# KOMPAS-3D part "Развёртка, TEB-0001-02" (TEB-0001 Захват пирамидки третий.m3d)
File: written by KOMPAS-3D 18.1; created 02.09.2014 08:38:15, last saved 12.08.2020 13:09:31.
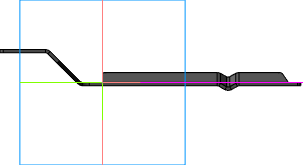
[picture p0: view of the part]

Document properties: Автор: user; Полное имя файла: F:\Чертежи\ЧАЙ\TSUBAKI\TEB\TEB-0001 и TEB-0001-01\TEB-0001 Захват пирамидки третий.m3d

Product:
- Part/product: Развёртка  | designation TEB-0001-02
    Материал: Лист$d1 ГОСТ 19904-90;12Х18Н9Т-Н1 ГОСТ 7350-77$ (density 7900 kg/m3)
    Масса: 0.028285
    source file: TEB-0001 Захват пирамидки третий.cdw
- Part/product: Захват пирамидки третий (дальний)  | designation TEB-0001-01
    Материал: Лист$d1 ГОСТ 19904-90;12Х18Н9Т-Н1 ГОСТ 7350-77$ (density 7900 kg/m3)
    Масса: 0.0283916
- Part/product: Захват пирамидки третий (ближний)  | designation TEB-0001
    Материал: Лист$d1 ГОСТ 19904-90;12Х18Н9Т-Н1 ГОСТ 7350-77$ (density 7900 kg/m3)
    Масса: 0.0283916
    source file: TEB-0001 Захват пирамидки третий.cdw

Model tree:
1. Эскиз:1
2. Листовое тело:1
     Расстояние 1 = 40
3. Сгиб(1) - Листовое тело:1
     Радиус сгиба = 1; Коэффициент = 0.421; Величина сгиба = 10
4. Сгиб(2) - Листовое тело:1
     Радиус сгиба = 1; Коэффициент = 0.421; Величина сгиба = 10
5. Сгиб(3) - Листовое тело:1
     Радиус сгиба = 1; Коэффициент = 0.421; Величина сгиба = 10
6. Эскиз:2  (with: Листовое тело:1)
7. Вырез в листовом теле:1
     Глубина выреза = 10
8. Эскиз:3  (with: Листовое тело:1)
9. Листовое тело:2
     Расстояние 1 = 40.5
10. Эскиз:4  (with: Листовое тело:2)
11. Вырез в листовом теле:2
     Глубина выреза = 10
12. Эскиз:7  (with: Листовое тело:2, Вырез в листовом теле:2)
13. Сгиб по линии:1
14. Сгиб(1) - Сгиб по линии:1  (with: Листовое тело:2)
     Радиус сгиба = 1; Коэффициент = 0.421; Величина сгиба = 10; Толщина листового тела = 1; Угол сгиба = 45
15. Эскиз:8  (with: Листовое тело:2)
16. Сгиб по линии:2
17. Сгиб(1) - Сгиб по линии:2  (with: Листовое тело:2)
     Радиус сгиба = 1; Коэффициент = 0.421; Величина сгиба = 10; Толщина листового тела = 1; Угол сгиба = 45
18. Эскиз:9  (with: Листовое тело:2)
19. Вырез в листовом теле:3
     Глубина выреза = 10
20. Эскиз:10  (with: Листовое тело:2, Вырез в листовом теле:3)
21. Вырез в листовом теле:4
     Глубина выреза = 10
22. Эскиз:11  (with: Листовое тело:2, Листовое тело:1)
23. Сгиб по линии:3
24. Сгиб(1) - Сгиб по линии:3  (with: Листовое тело:2)
     Радиус сгиба = 1; Коэффициент = 0.421; Величина сгиба = 10; Толщина листового тела = 1; Угол сгиба = 15
25. Сгиб по линии:4
26. Сгиб(1) - Сгиб по линии:4  (with: Листовое тело:1)
     Радиус сгиба = 1; Коэффициент = 0.421; Величина сгиба = 10; Толщина листового тела = 1; Угол сгиба = 15
27. Эскиз:12  (with: Листовое тело:1, Сгиб по линии:3, Сгиб по линии:4)
28. Вырезать элемент выдавливания:1  (with: Сгиб по линии:3)
     Расстояние 1 = 12
29. Эскиз:13  (with: Листовое тело:1)
30. Листовое тело:3
     Расстояние 2 = 11.628
31. Сгиб(1) - Листовое тело:3
     Радиус сгиба = 1; Коэффициент = 0.421; Величина сгиба = 10
32. Сгиб(2) - Листовое тело:3
     Радиус сгиба = 1; Коэффициент = 0.421; Величина сгиба = 10
33. Сгиб(3) - Листовое тело:3
     Радиус сгиба = 1; Коэффициент = 0.421; Величина сгиба = 10
34. Эскиз:14  (with: Сгиб по линии:4, Вырезать элемент выдавливания:1, Сгиб по линии:3)
35. Эскиз:15  (with: Листовое тело:3)
36. Операция по сечениям:1
     Толщина стенки 1 = 1; Толщина стенки 2 = 1
37. Скругление:1  (with: Вырез в листовом теле:3, Листовое тело:1, Вырез в листовом теле:1)
     Радиус = 1
38. Развертка  (with: Листовое тело:2)  (labels: Лист$d1 ГОСТ 19904-90;12Х18Н9Т-Н1 ГОСТ 7350-77$; TEB-0001|SM_Thickness; TEB-0001|SM_Radius; TEB-0001|SM_K)
39. Эскиз:16
40. Листовое тело:4
     Расстояние 1 = 10; Радиус сгиба = 1

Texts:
  TEB-0001
  TEB-0001|SM_BA
  TEB-0001|SM_BD
  TEB-0001|SM_Angle
  TEB-0001|SM_H
  TEB-0001|SM_W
